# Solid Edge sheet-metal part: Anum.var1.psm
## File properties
Author: jaanm
Template: ansi metric sheet metal.psm
Last saved by: jaanm
Revision: 4
Application: Solid Edge
Accuracy: 0,990
Material Thickness: 5,00 mm
Bend Radius: 1,00 mm
Relief Width: 1,00 mm
Relief Length: 0,00 mm
Neutral Factor: 0,330
Minimum Arc Length: 0,10 mm
Deviational Tolerance: 0,10 mm
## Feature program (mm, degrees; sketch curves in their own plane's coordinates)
material thickness "unnamed MaterialThickness 1"
louver "Louver_1"
base feature "unnamed BaseFeature 1"
flange "Flange_9"
flange "Flange_10"
bead "unnamed Bead 1"
close corner "CloseCorner_7"
close corner "CloseCorner_8"
dimple "Dimple_1"
dimple "Dimple_2"
chamfer "Chamfer_1" setback 5
gusset "Gusset_1"  Offset_From_Bend = 23.3382 mm
mirror "unnamed Mirror 1" of "Gusset_1" about plane through (0, 0, 0) normal (1, 0, 0)
gusset "unnamed Gusset 1"
sketch for "Hole_1" plane through (-255, 146.9645, 155.5) normal (-1, 0, 0) x-axis (0, -1, 0)
  hole centre (146.9645, 97.5973) bore radius 5
hole "Hole_1"
sketch for "unnamed Hole 1" plane through (-255, 146.9645, 155.5) normal (-1, 0, 0) x-axis (0, -1, 0)
  hole centre (246.9645, 97.5973) bore radius 5
hole "unnamed Hole 1"
pattern "unnamed Pattern 1" of "Hole_1", "unnamed Hole 1"
mirror "unnamed Mirror 2" of "unnamed Pattern 1" about plane through (0, 0, 0) normal (1, 0, 0)
hole "unnamed Hole 2"
hole "unnamed Hole 3"
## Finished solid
Body 1: solid body, 141 faces, 333 edges, 194 vertices.
  Faces by surface: plane 81, cylinder 52, sphere 4, torus 4
  Edges by curve: line 223, circle 60, ellipse 50
Bounding box of the edges (mm; curved faces can reach further): 510.000 x 1042.727 x 336.049, from (-255, -374, -30) to (255, 668.7269, 306.0493).
Cylindrical faces by radius (mm): R1 x8, R2.5 x2, R5 x30, R6 x8, R7.5 x2, R27.5 x1, R32.5 x1
Toroidal faces (ring radius, tube radius in mm): R31.6697 r5 x1, R50 r15 x1, R50 r20 x1, R68.3303 r5 x1
Spherical faces by radius (mm): R27.5 x2, R32.5 x2
Planar faces by outward normal: +x 6, +y 10, +z 7, -x 7, -y 12, -z 5, oblique 34
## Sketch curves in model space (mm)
spline (-17.37, 558.488, 213.488) -> (-0.4907, 558.488, 213.488) -> (16.3886, 558.488, 213.488)
spline (-100, 420.9526, 75.9526) -> (-58.685, 489.7203, 144.7203) -> (-17.37, 558.488, 213.488)
spline (-63.6899, 420.9526, 75.9526) -> (-81.8449, 420.9526, 75.9526) -> (-100, 420.9526, 75.9526)
spline (-0.2944, 529.8984, 184.8984) -> (-31.9921, 475.4255, 130.4255) -> (-63.6899, 420.9526, 75.9526)
spline (63.6899, 420.9526, 75.9526) -> (31.6977, 475.4255, 130.4255) -> (-0.2944, 529.8984, 184.8984)
spline (100, 420.9526, 75.9526) -> (81.8449, 420.9526, 75.9526) -> (63.6899, 420.9526, 75.9526)
spline (16.3886, 558.488, 213.488) -> (58.1943, 489.7203, 144.7203) -> (100, 420.9526, 75.9526)
line (0, -10, -30) -> (0, 10, -30)
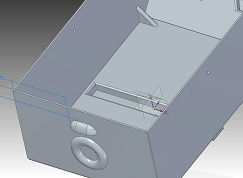
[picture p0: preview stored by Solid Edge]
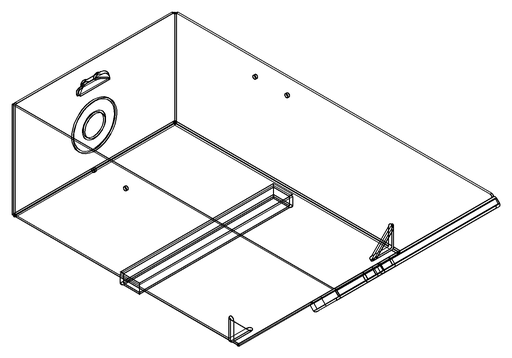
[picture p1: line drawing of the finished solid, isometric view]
